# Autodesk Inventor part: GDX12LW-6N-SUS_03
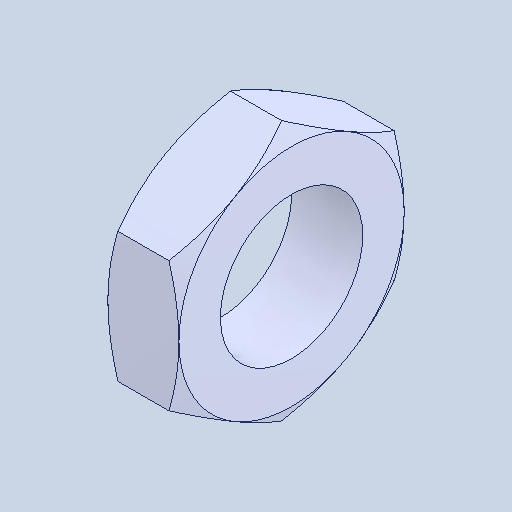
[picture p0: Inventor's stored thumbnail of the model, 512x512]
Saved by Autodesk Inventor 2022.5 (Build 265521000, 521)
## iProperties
Created: 2024-06
Part Number: GDX12LW-6N-SUS_03
Material: 一般
Document SubType Name: Modeling
Designer: ImaoCorp
Density: 1 g/cm^3
Appearance: 既定
Author: ImaoCorp
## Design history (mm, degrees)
feature "GDX12LW-6N-SUS_03"
node "ソリッド1"
